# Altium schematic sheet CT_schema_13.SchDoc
size 386 x 278 mm
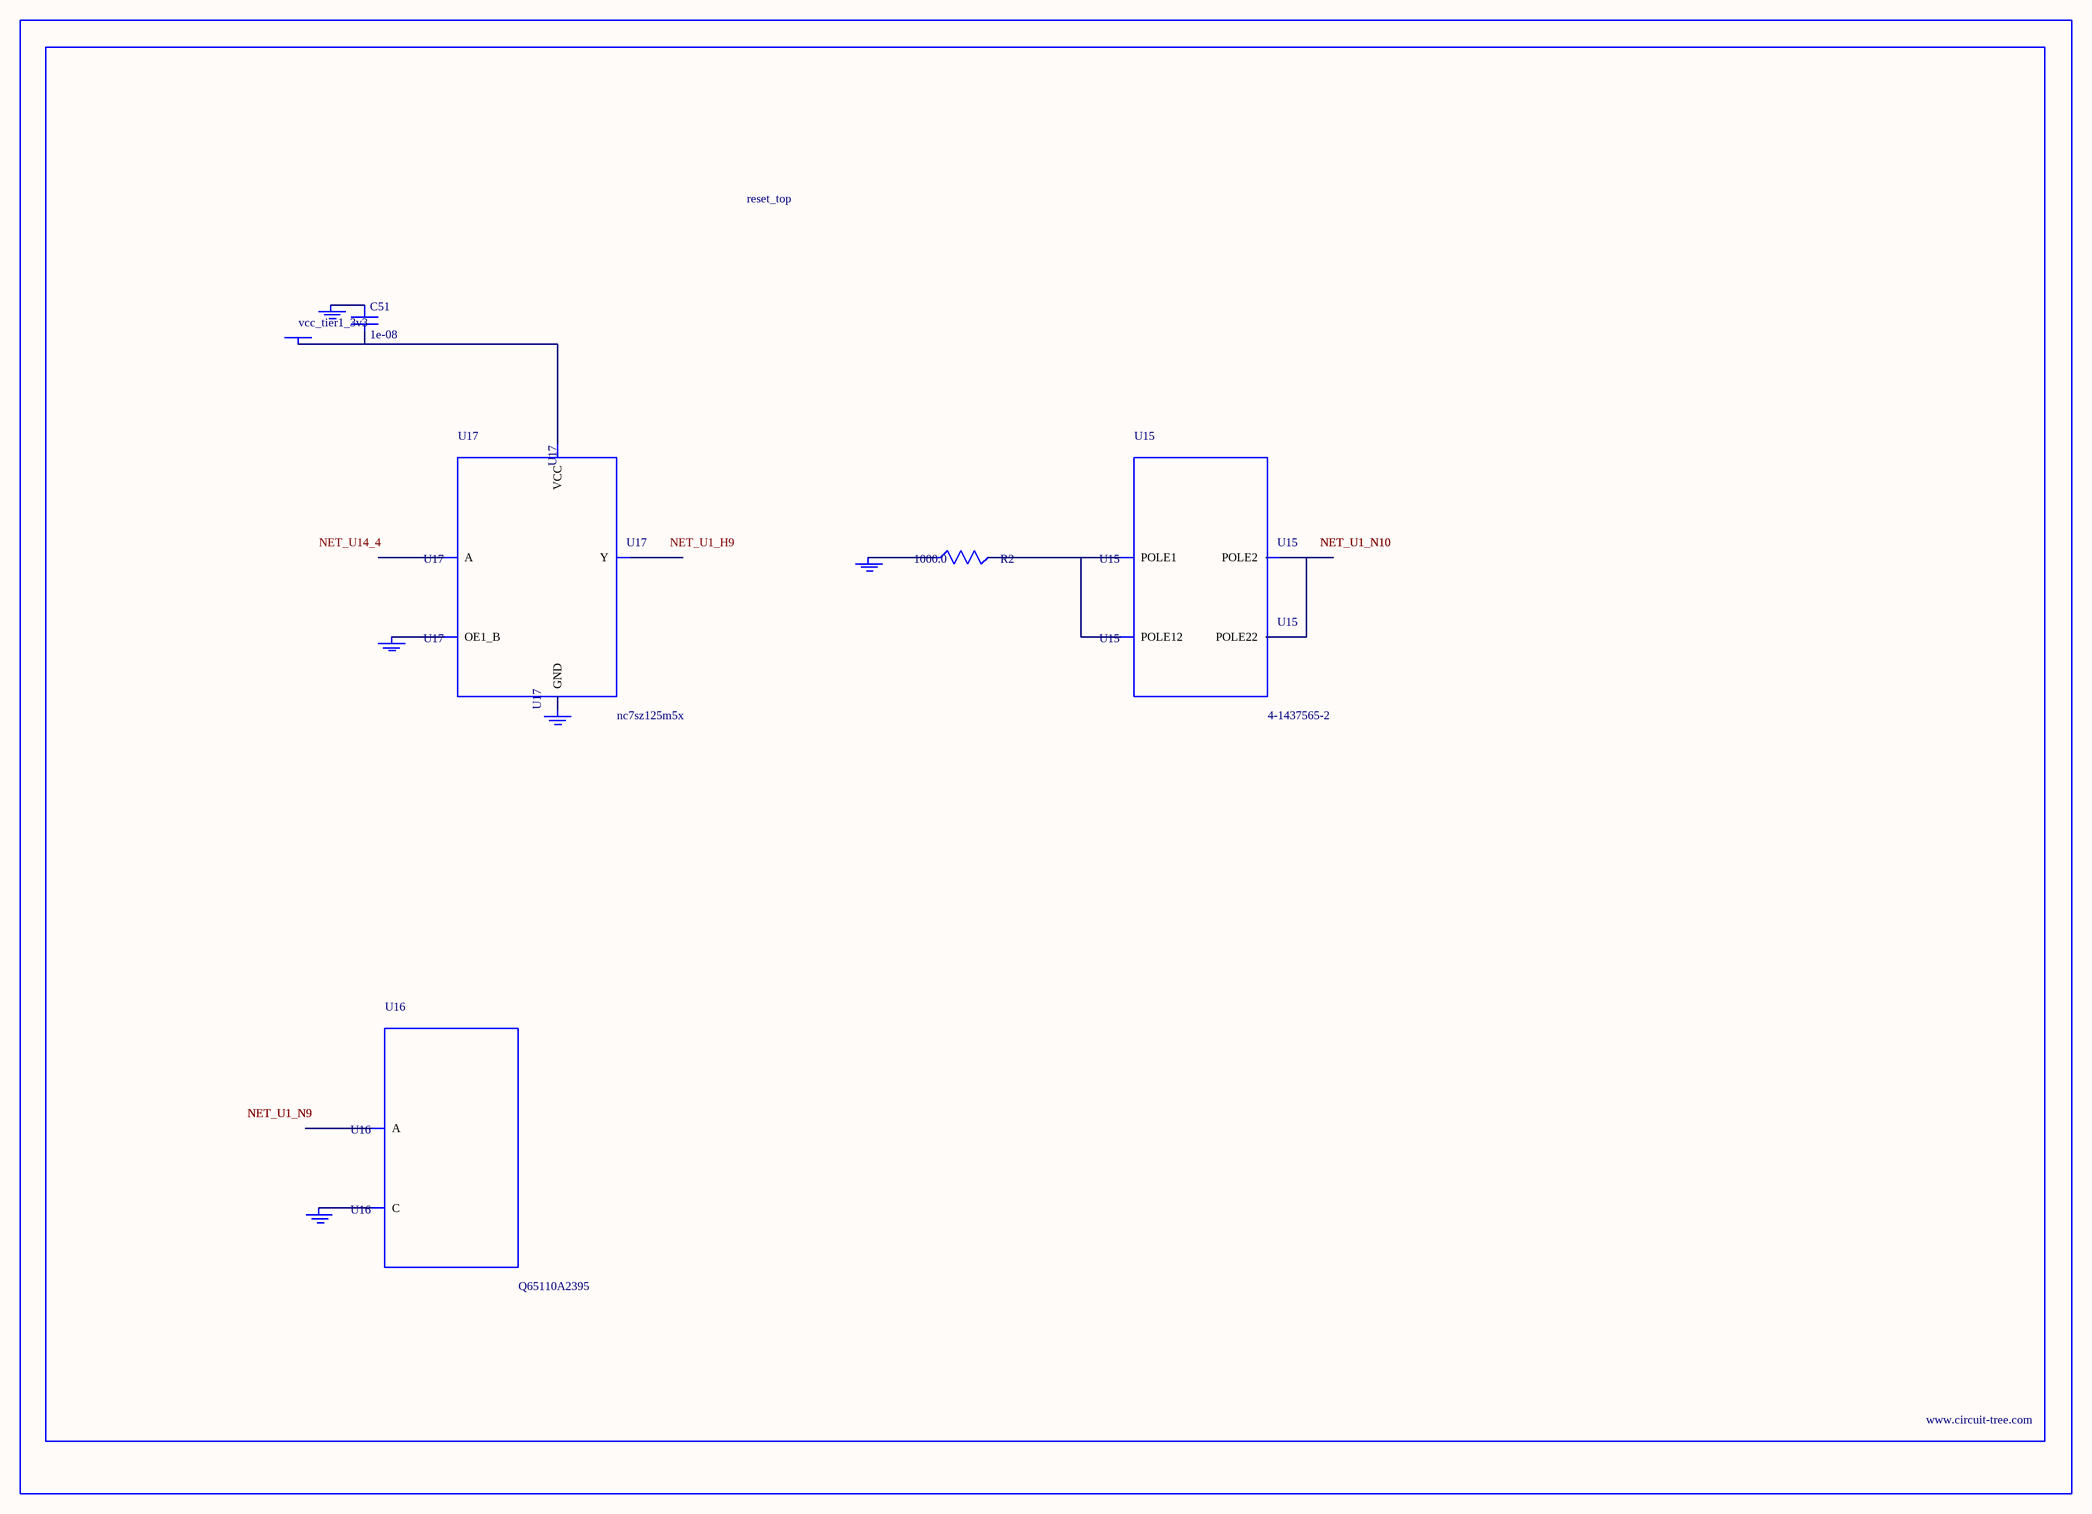
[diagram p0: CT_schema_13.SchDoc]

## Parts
BORDER12  (no value)
C51  1e-08  [C0402]
GND_INSTANCE_12_0  (no value)
GND_INSTANCE_12_1  (no value)
GND_INSTANCE_12_2  (no value)
GND_INSTANCE_12_3  (no value)
GND_INSTANCE_12_4  (no value)
POWER_INSTANCE_12_0  vcc_tier1_3v3
R2  1000.0  [R0603]
U15  4-1437565-2  [SW_4-1437565-2]
U16  Q65110A2395  [LGM67K-G1J2-24-Z]
U17  nc7sz125m5x  [NC7SZ125M5X]

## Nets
NetC51_1: C51.1 GND_INSTANCE_12_2.0(GND)
NetC51_2: C51.2 POWER_INSTANCE_12_0.0(PWR) U17.5(VCC)
NetGND_INSTANCE_12_0_0: GND_INSTANCE_12_0.0(GND) R2.1
NetGND_INSTANCE_12_1_0: GND_INSTANCE_12_1.0(GND) U16.C
NetGND_INSTANCE_12_3_0: GND_INSTANCE_12_3.0(GND) U17.1(OE1_B)
NetGND_INSTANCE_12_4_0: GND_INSTANCE_12_4.0(GND) U17.3(GND)
NetR2_2: R2.2 U15.1(POLE1) U15.2(POLE12)
NetU15_3: U15.3(POLE2) U15.4(POLE22)

Not connected (* = marked no-connect by the designer): U16 A; U17 2(A) 4(Y)

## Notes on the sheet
- Labels drawn without touching a wire or pin: NET_U1_H9, NET_U14_4

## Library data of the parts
BORDER12 = BORDER_PAGE12
C51 = C0402C103K3RAC
GND_INSTANCE_12_0-GND_INSTANCE_12_4 = GND
POWER_INSTANCE_12_0 = PWR
R2 = RC0603JR-071KL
